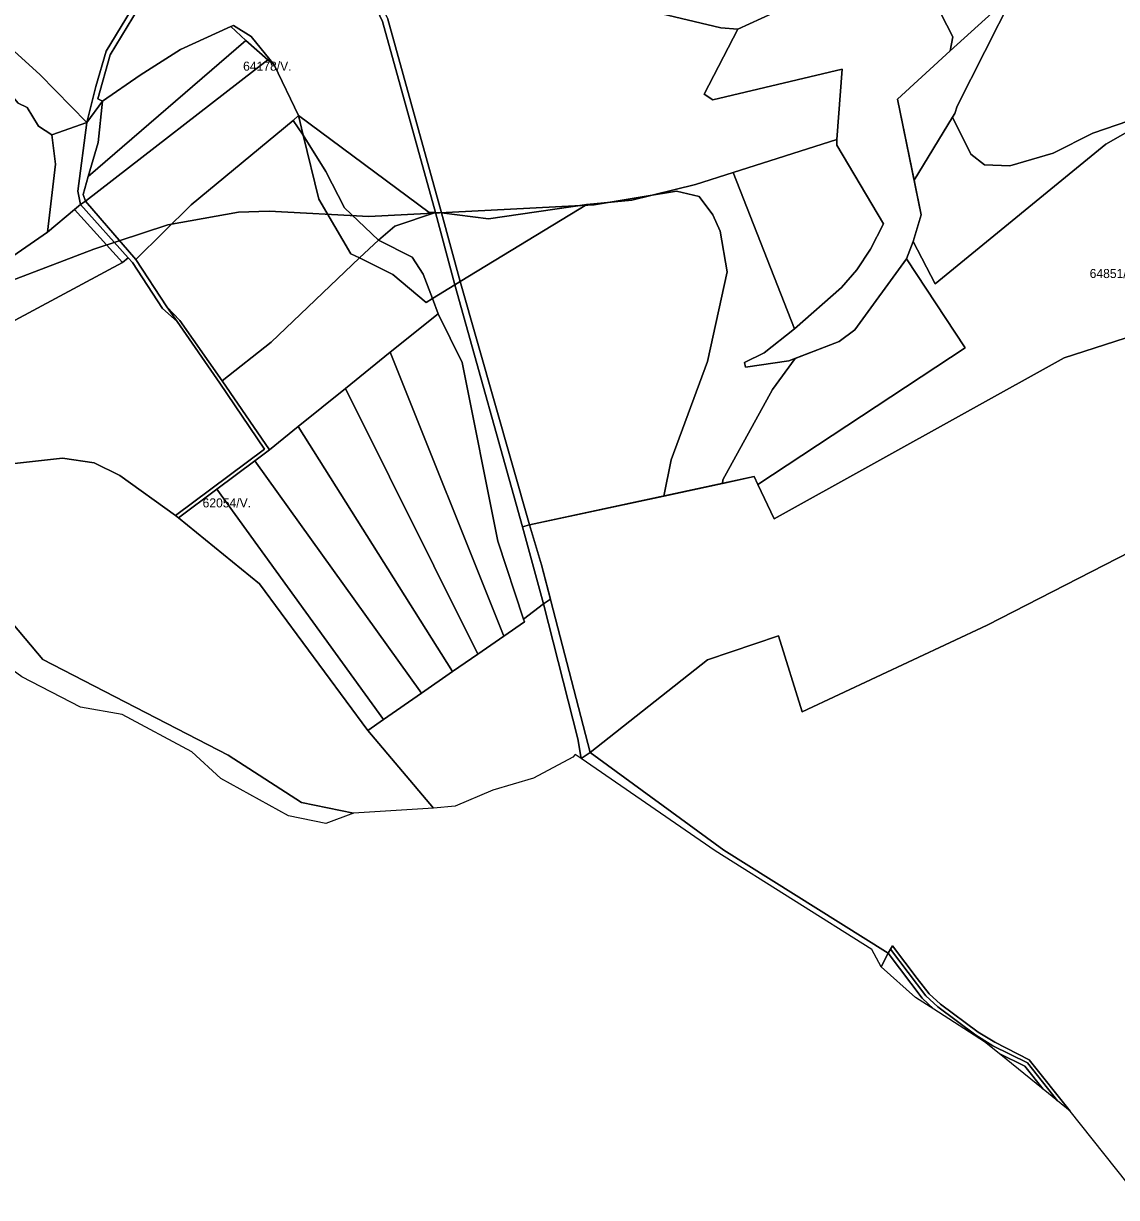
# Model space of a CAD drawing. Extents: x -521261 to -517465, y -1182764 to -1179456.
# Drawn here: x -518839 to -518235, y -1182709 to -1182060 of the extents above; entities that cross this region are included whole.
import ezdxf

# ---------------------------------------------------------------- set-up
doc = ezdxf.new("R2010")
doc.units = 0
for name, color, linetype in [('95560013', 7, 'Continuous'), ('95610013', 7, 'Continuous'), ('95620013', 7, 'Continuous'), ('95640013', 7, 'Continuous'), ('95660013', 7, 'Continuous')]:
    doc.layers.add(name, color=color, linetype=linetype)

msp = doc.modelspace()

# ---------------------------------------------------------------- linework, layer by layer
at = {"layer": '95560013'}
for points in [[(-517937.47, -1181926.51), (-517884.7, -1181968.01), (-518025.29, -1182113.9), (-518027.56, -1182111.28), (-518111.08, -1182158.35), (-518153.43, -1182170.1), (-518139.38, -1182204.87), (-518263.83, -1182245.02), (-518424.06, -1182333.99), (-518433.13, -1182315.06), (-518318.58, -1182239.54), (-518350.96, -1182190.35), (-518347.31, -1182180.7), (-518335.12, -1182204.11), (-518240.87, -1182127.03), (-518183.99, -1182094.63), (-518090.51, -1182068.93), (-518110.82, -1182018.11), (-518086.87, -1182044.67), (-518069.54, -1182031.68), (-518065.44, -1182028.22), (-518074.66, -1182003.92), (-518054.75, -1182013.18), (-518003.38, -1181979.84)], [(-518167.73, -1181955), (-518110.82, -1182018.11), (-518090.51, -1182068.93), (-518183.99, -1182094.63), (-518240.87, -1182127.03), (-518335.12, -1182204.11), (-518347.31, -1182180.7), (-518342.86, -1182166.04), (-518356.01, -1182102.22), (-518326.89, -1182075.42), (-518296.03, -1182047.39), (-518203.6, -1181987.3), (-518203.86, -1181976.19)], [(-518700.25, -1182083.11), (-518686.86, -1182111.13), (-518689.9, -1182113.86), (-518746.1, -1182160.51), (-518776.69, -1182190.71), (-518804.47, -1182158.53), (-518703.84, -1182080.32)], [(-518689.9, -1182113.86), (-518684.29, -1182121.97), (-518675.72, -1182157.46), (-518658.04, -1182187.51), (-518653.23, -1182189.87), (-518702, -1182236.38), (-518728.96, -1182257.76), (-518752.35, -1182224.39), (-518759.58, -1182216.94), (-518776.69, -1182190.71), (-518746.1, -1182160.51)], [(-518689.9, -1182113.86), (-518686.86, -1182111.13), (-518684.29, -1182121.97)], [(-518686.86, -1182111.13), (-518614.61, -1182164.68), (-518611.24, -1182164.8), (-518633.66, -1182172.36), (-518642.72, -1182180.05), (-518661.49, -1182162.15), (-518671.83, -1182142.12), (-518684.29, -1182121.97)], [(-518684.29, -1182121.97), (-518671.83, -1182142.12), (-518661.49, -1182162.15), (-518642.72, -1182180.05), (-518653.23, -1182189.87), (-518658.04, -1182187.51), (-518675.72, -1182157.46)], [(-518446.76, -1182142.75), (-518412.83, -1182229.01), (-518429.66, -1182242.3), (-518440.48, -1182247.57), (-518439.99, -1182250.28), (-518416.09, -1182246.77), (-518388.22, -1182235.99), (-518379.47, -1182229.52), (-518350.96, -1182190.35), (-518318.58, -1182239.54), (-518433.13, -1182315.06), (-518435.2, -1182310.64), (-518559.26, -1182337.41), (-518597.56, -1182202.93), (-518527.66, -1182160.32), (-518502.65, -1182158.02), (-518467.48, -1182149.36)], [(-518804.47, -1182158.53), (-518776.69, -1182190.71), (-518759.58, -1182216.94), (-518753.86, -1182224.98), (-518761.94, -1182217.74), (-518778.49, -1182192.42), (-518780.9, -1182189.83), (-518807.22, -1182160.43)], [(-518810.55, -1182163.14), (-518784.05, -1182192.34), (-518855.87, -1182230.85), (-518949.78, -1182265.77), (-518957.97, -1182261.15), (-518966.08, -1182237.71), (-518940.53, -1182228.04), (-518928.17, -1182223.92), (-518863.4, -1182201.85), (-518825.45, -1182175.55)], [(-518807.22, -1182160.43), (-518780.9, -1182189.83), (-518784.05, -1182192.34), (-518810.55, -1182163.14)], [(-518611.24, -1182164.8), (-518600.56, -1182204.73), (-518612.93, -1182212.35), (-518617.97, -1182198.92), (-518624.12, -1182189.53), (-518642.72, -1182180.05), (-518633.66, -1182172.36)], [(-518607.85, -1182165.03), (-518597.56, -1182202.93), (-518600.56, -1182204.73), (-518611.24, -1182164.8)], [(-518527.66, -1182160.32), (-518597.56, -1182202.93), (-518607.85, -1182165.03), (-518581.87, -1182168.26)], [(-518624.12, -1182189.53), (-518617.97, -1182198.92), (-518612.93, -1182212.35), (-518616.36, -1182214.44), (-518634.78, -1182198.94), (-518653.23, -1182189.87), (-518642.72, -1182180.05)], [(-518784.05, -1182192.34), (-518780.9, -1182189.83), (-518778.49, -1182192.42), (-518761.94, -1182217.74), (-518753.86, -1182224.98), (-518730.33, -1182259.05), (-518705.7, -1182295.48), (-518754.91, -1182332.21), (-518785.58, -1182309.98), (-518799.71, -1182303), (-518817.23, -1182300.45), (-518852.15, -1182304.44), (-518880.01, -1182306.19), (-518905.94, -1182299.56), (-518929.3, -1182288.2), (-518949.78, -1182265.77), (-518855.87, -1182230.85)], [(-518653.23, -1182189.87), (-518634.78, -1182198.94), (-518616.36, -1182214.44), (-518612.93, -1182212.35), (-518609.8, -1182220.66), (-518636.22, -1182242), (-518660.98, -1182261.99), (-518687.02, -1182283.01), (-518702.93, -1182295.87), (-518728.96, -1182257.76), (-518702, -1182236.38)], [(-518612.93, -1182212.35), (-518600.56, -1182204.73), (-518563.11, -1182338.38), (-518551.47, -1182380.97), (-518562.67, -1182389.49), (-518576.74, -1182346.42), (-518596.5, -1182247.68), (-518609.8, -1182220.66)], [(-518597.56, -1182202.93), (-518559.26, -1182337.41), (-518563.11, -1182338.38), (-518600.56, -1182204.73)], [(-518759.58, -1182216.94), (-518752.35, -1182224.39), (-518728.96, -1182257.76), (-518702.93, -1182295.87), (-518711.08, -1182301.98), (-518731.97, -1182317.68), (-518753.1, -1182333.54), (-518754.91, -1182332.21), (-518705.7, -1182295.48), (-518730.33, -1182259.05), (-518753.86, -1182224.98)], [(-518636.22, -1182242), (-518609.8, -1182220.66), (-518596.5, -1182247.68), (-518576.74, -1182346.42), (-518562.67, -1182389.49), (-518562.01, -1182390.85), (-518573.44, -1182398.77)], [(-518660.98, -1182261.99), (-518636.22, -1182242), (-518573.44, -1182398.77), (-518587.82, -1182408.73)], [(-518687.02, -1182283.01), (-518660.98, -1182261.99), (-518587.82, -1182408.73), (-518601.78, -1182418.4)], [(-518702.93, -1182295.87), (-518687.02, -1182283.01), (-518601.78, -1182418.4), (-518618.86, -1182430.24), (-518711.08, -1182301.98)], [(-518799.71, -1182303), (-518785.58, -1182309.98), (-518754.91, -1182332.21), (-518753.1, -1182333.54), (-518708.42, -1182369.96), (-518648.65, -1182450.88), (-518612.29, -1182493.83), (-518656.41, -1182496.56), (-518685.18, -1182490.81), (-518725.77, -1182464.65), (-518828.06, -1182411.68), (-518865.37, -1182367.72), (-518852.15, -1182304.44), (-518817.23, -1182300.45)], [(-518731.97, -1182317.68), (-518711.08, -1182301.98), (-518618.86, -1182430.24), (-518640.01, -1182444.89)], [(-518753.1, -1182333.54), (-518731.97, -1182317.68), (-518640.01, -1182444.89), (-518648.65, -1182450.88), (-518708.42, -1182369.96)]]:
    msp.add_lwpolyline(points, close=True, dxfattribs=at)
at = {"layer": '95610013'}
for points in [[(-518762.93, -1181945.84), (-518735.59, -1181944.64), (-518720.24, -1181948.49), (-518709.38, -1181958.17), (-518725.01, -1181970.47), (-518741.93, -1181991.3), (-518793.08, -1182075.55), (-518798.87, -1182095.21), (-518803.83, -1182115.05), (-518829.83, -1182088.59), (-518858.12, -1182062.9), (-518889.08, -1182041.43), (-518875.98, -1182033.84), (-518827.3, -1181989.81), (-518772.88, -1181947.46)], [(-518708.15, -1181959.43), (-518724.45, -1181974.21), (-518740.82, -1181994.92), (-518790.95, -1182077.71), (-518797.78, -1182101.99), (-518795.23, -1182103.31), (-518803.83, -1182115.05), (-518798.87, -1182095.21), (-518793.08, -1182075.55), (-518741.93, -1181991.3), (-518725.01, -1181970.47), (-518709.38, -1181958.17)], [(-518724.45, -1181974.21), (-518708.15, -1181959.43), (-518686.54, -1181980.93), (-518658.7, -1182020.15), (-518640.52, -1182059.28), (-518611.24, -1182164.8), (-518614.61, -1182164.68), (-518686.86, -1182111.13), (-518700.25, -1182083.11), (-518713.09, -1182067.46), (-518722.81, -1182061.39), (-518724.32, -1182062.07), (-518751.97, -1182074.61), (-518774.42, -1182088.9), (-518795.23, -1182103.31), (-518797.78, -1182101.99), (-518790.95, -1182077.71), (-518740.82, -1181994.92)], [(-518510.09, -1182043.38), (-518444.47, -1182035.28), (-518420.88, -1182053.43), (-518424.84, -1182054.69), (-518444.19, -1182063.4), (-518453.63, -1182062.64), (-518490.02, -1182054.06), (-518504.2, -1182054.05)], [(-518724.32, -1182062.07), (-518715.88, -1182069.82), (-518802.99, -1182144.82), (-518797.55, -1182126.13), (-518795.23, -1182103.31), (-518774.42, -1182088.9), (-518751.97, -1182074.61)], [(-518722.81, -1182061.39), (-518713.09, -1182067.46), (-518700.25, -1182083.11), (-518703.84, -1182080.32), (-518715.88, -1182069.82), (-518724.32, -1182062.07)], [(-518865.04, -1182069.45), (-518861.95, -1182080.69), (-518853.17, -1182091.09), (-518841.68, -1182104.3), (-518836.85, -1182106.7), (-518830.45, -1182117.06), (-518823.16, -1182121.89), (-518821.12, -1182138.11), (-518825.45, -1182175.55), (-518863.4, -1182201.85), (-518928.17, -1182223.92), (-518954.27, -1182165.24), (-518970.44, -1182168.59), (-518984.8, -1182153.5), (-519002.24, -1182131.47), (-518974.87, -1182115.84), (-518955.62, -1182102.6), (-518935.43, -1182082.05), (-518859.47, -1182146.72), (-518853.31, -1182128.3), (-518897.42, -1182099.88), (-518890.47, -1182081.22), (-518878.76, -1182064.07)], [(-518703.84, -1182080.32), (-518804.47, -1182158.53), (-518805.75, -1182154.86), (-518802.99, -1182144.82), (-518715.88, -1182069.82)], [(-518795.23, -1182103.31), (-518797.55, -1182126.13), (-518802.99, -1182144.82), (-518805.75, -1182154.86), (-518804.47, -1182158.53), (-518807.22, -1182160.43), (-518808.76, -1182153.03), (-518803.83, -1182115.05)], [(-518803.83, -1182115.05), (-518808.76, -1182153.03), (-518807.22, -1182160.43), (-518810.55, -1182163.14), (-518825.45, -1182175.55), (-518821.12, -1182138.11), (-518823.16, -1182121.89)], [(-518389.49, -1182127.53), (-518363.62, -1182170.97), (-518370.83, -1182185.07), (-518378.46, -1182196.42), (-518386.94, -1182206.15), (-518412.83, -1182229.01), (-518446.76, -1182142.75), (-518389.43, -1182124.42)]]:
    msp.add_lwpolyline(points, close=True, dxfattribs=at)
msp.add_lwpolyline([(-518490.02, -1182054.06), (-518453.63, -1182062.64), (-518444.19, -1182063.4), (-518462.82, -1182099.41), (-518458.01, -1182102.44), (-518386.6, -1182085.52), (-518389.43, -1182124.42), (-518446.76, -1182142.75), (-518467.48, -1182149.36), (-518502.65, -1182158.02), (-518527.66, -1182160.32), (-518581.87, -1182168.26), (-518607.85, -1182165.03), (-518637.52, -1182058.03)], dxfattribs=at)
at = {"layer": '95620013'}
for points in [[(-518332.06, -1182054.74), (-518325.37, -1182067.68), (-518326.89, -1182075.42), (-518356.01, -1182102.22), (-518342.86, -1182166.04), (-518347.31, -1182180.7), (-518350.96, -1182190.35), (-518379.47, -1182229.52), (-518388.22, -1182235.99), (-518416.09, -1182246.77), (-518439.99, -1182250.28), (-518440.48, -1182247.57), (-518429.66, -1182242.3), (-518412.83, -1182229.01), (-518386.94, -1182206.15), (-518378.46, -1182196.42), (-518370.83, -1182185.07), (-518363.62, -1182170.97), (-518389.49, -1182127.53), (-518389.43, -1182124.42), (-518386.6, -1182085.52), (-518458.01, -1182102.44), (-518462.82, -1182099.41), (-518444.19, -1182063.4), (-518424.84, -1182054.69)], [(-518222.72, -1182708.99), (-518260.64, -1182661.33), (-518283.21, -1182633), (-518302.23, -1182623.19), (-518311.5, -1182617.7), (-518332.22, -1182602.24), (-518338.45, -1182596.45), (-518345.09, -1182588.03), (-518358.72, -1182569.94), (-518359.91, -1182571.84), (-518361.09, -1182574.04), (-518451.99, -1182517.08), (-518525.73, -1182463.17), (-518461.02, -1182411.93), (-518421.69, -1182398.59), (-518408.71, -1182440.57), (-518306.45, -1182392.72), (-518147.76, -1182311.32)]]:
    msp.add_lwpolyline(points, dxfattribs=at)
for points in [[(-518025.29, -1182113.9), (-518132.88, -1182226.29), (-518107.95, -1182268.17), (-518147.76, -1182311.32), (-518306.45, -1182392.72), (-518408.71, -1182440.57), (-518421.69, -1182398.59), (-518461.02, -1182411.93), (-518525.73, -1182463.17), (-518552.56, -1182359.4), (-518559.26, -1182337.41), (-518435.2, -1182310.64), (-518433.13, -1182315.06), (-518424.06, -1182333.99), (-518263.83, -1182245.02), (-518139.38, -1182204.87), (-518153.43, -1182170.1), (-518111.08, -1182158.35), (-518027.56, -1182111.28)], [(-518562.67, -1182389.49), (-518551.47, -1182380.97), (-518532.52, -1182455.61), (-518530.75, -1182466.4), (-518534.03, -1182464.13), (-518535.31, -1182465.71), (-518557.06, -1182477.23), (-518579.44, -1182483.85), (-518600.27, -1182492.68), (-518612.29, -1182493.83), (-518648.65, -1182450.88), (-518640.01, -1182444.89), (-518618.86, -1182430.24), (-518601.78, -1182418.4), (-518587.82, -1182408.73), (-518573.44, -1182398.77), (-518562.01, -1182390.85)], [(-518361.09, -1182574.04), (-518342.38, -1182598.83), (-518335.95, -1182604.96), (-518346.01, -1182598.51), (-518365, -1182581.49)], [(-518359.91, -1182571.84), (-518340.25, -1182597.6), (-518333.74, -1182603.69), (-518312.76, -1182619.3), (-518303.39, -1182625.12), (-518284.15, -1182634.6), (-518267.61, -1182655.55), (-518275.54, -1182649.17), (-518285.56, -1182636.5), (-518299.9, -1182629.46), (-518307.86, -1182623), (-518335.95, -1182604.96), (-518342.38, -1182598.83), (-518361.09, -1182574.04)], [(-518358.72, -1182569.94), (-518345.09, -1182588.03), (-518338.45, -1182596.45), (-518332.22, -1182602.24), (-518311.5, -1182617.7), (-518302.23, -1182623.19), (-518283.21, -1182633), (-518260.64, -1182661.33), (-518267.61, -1182655.55), (-518284.15, -1182634.6), (-518303.39, -1182625.12), (-518312.76, -1182619.3), (-518333.74, -1182603.69), (-518340.25, -1182597.6), (-518359.91, -1182571.84)], [(-518299.9, -1182629.46), (-518285.56, -1182636.5), (-518275.54, -1182649.17)]]:
    msp.add_lwpolyline(points, close=True, dxfattribs=at)
at = {"layer": '95640013'}
for points in [[(-518167.73, -1181955), (-518203.86, -1181976.19), (-518203.6, -1181987.3), (-518296.03, -1182047.39), (-518326.89, -1182075.42), (-518325.37, -1182067.68), (-518332.06, -1182054.74), (-518189.71, -1181930.34)], [(-518735.03, -1181941.6), (-518718.84, -1181946.08), (-518684.26, -1181979.3), (-518656.15, -1182018.67), (-518637.52, -1182058.03), (-518607.85, -1182165.03), (-518611.24, -1182164.8), (-518640.52, -1182059.28), (-518658.7, -1182020.15), (-518686.54, -1181980.93), (-518708.15, -1181959.43), (-518709.38, -1181958.17), (-518720.24, -1181948.49), (-518735.59, -1181944.64), (-518762.93, -1181945.84), (-518772.88, -1181947.46), (-518768, -1181943.45), (-518760.29, -1181942.5)], [(-518880.73, -1182050.39), (-518889.08, -1182041.43), (-518858.12, -1182062.9), (-518829.83, -1182088.59), (-518803.83, -1182115.05), (-518823.16, -1182121.89), (-518830.45, -1182117.06), (-518836.85, -1182106.7), (-518841.68, -1182104.3), (-518853.17, -1182091.09), (-518861.95, -1182080.69), (-518865.04, -1182069.45), (-518878.76, -1182064.07), (-518876.94, -1182060.89)], [(-518563.11, -1182338.38), (-518559.26, -1182337.41), (-518552.56, -1182359.4), (-518525.73, -1182463.17), (-518530.75, -1182466.4), (-518532.52, -1182455.61), (-518551.47, -1182380.97)], [(-518865.37, -1182367.72), (-518828.06, -1182411.68), (-518725.77, -1182464.65), (-518685.18, -1182490.81), (-518656.41, -1182496.56), (-518671.74, -1182502.4), (-518692.39, -1182498.07), (-518729.72, -1182477.4), (-518745.79, -1182462.67), (-518784.2, -1182442.1), (-518807.32, -1182438.02), (-518839.75, -1182421.31), (-518846.6, -1182416.39), (-518872.51, -1182380.67)], [(-518525.73, -1182463.17), (-518451.99, -1182517.08), (-518361.09, -1182574.04), (-518365, -1182581.49), (-518370.23, -1182571.92), (-518456.78, -1182517.53), (-518530.75, -1182466.4)]]:
    msp.add_lwpolyline(points, close=True, dxfattribs=at)
at = {"layer": '95660013'}
for points in [[(-518228, -1182006), (-518239, -1182007), (-518260.5, -1182013.5), (-518271.5, -1182021), (-518292.5, -1182045.5), (-518323, -1182106), (-518324.24, -1182110.04), (-518325.55, -1182112.16), (-518346.82, -1182146.82), (-518356.01, -1182102.22), (-518326.89, -1182075.42), (-518325.37, -1182067.68), (-518332.06, -1182054.74), (-518189.71, -1181930.34)], [(-518196, -1182103), (-518248, -1182121), (-518270, -1182132), (-518294, -1182139), (-518308, -1182138.5), (-518315.5, -1182132.5), (-518325.55, -1182112.16), (-518324.24, -1182110.04), (-518323, -1182106), (-518292.5, -1182045.5), (-518271.5, -1182021), (-518260.5, -1182013.5), (-518239, -1182007), (-518228, -1182006)], [(-518424.84, -1182054.69), (-518444.19, -1182063.4), (-518462.82, -1182099.41), (-518458.01, -1182102.44), (-518386.6, -1182085.52), (-518389.43, -1182124.42), (-518389.49, -1182127.53), (-518363.62, -1182170.97), (-518370.83, -1182185.07), (-518378.46, -1182196.42), (-518386.94, -1182206.15), (-518412.83, -1182229.01), (-518429.66, -1182242.3), (-518440.48, -1182247.57), (-518439.99, -1182250.28), (-518416.09, -1182246.77), (-518412.43, -1182245.35), (-518425, -1182262.5), (-518452.5, -1182312.5), (-518452.7, -1182314.42), (-518485.13, -1182321.41), (-518481, -1182301.5), (-518461, -1182247), (-518450, -1182197.5), (-518454, -1182175), (-518458, -1182166), (-518465.5, -1182156), (-518478, -1182153), (-518496, -1182156), (-518523.5, -1182160.5), (-518648, -1182167), (-518703, -1182164), (-518720, -1182164.5), (-518759, -1182171.5), (-518800, -1182185), (-518869.5, -1182211.5)], [(-518332.06, -1182054.74), (-518325.37, -1182067.68), (-518326.89, -1182075.42), (-518356.01, -1182102.22), (-518346.82, -1182146.82), (-518342.86, -1182166.04), (-518347.31, -1182180.7), (-518350.96, -1182190.35), (-518379.47, -1182229.52), (-518388.22, -1182235.99), (-518412.43, -1182245.35), (-518416.09, -1182246.77), (-518439.99, -1182250.28), (-518440.48, -1182247.57), (-518429.66, -1182242.3), (-518412.83, -1182229.01), (-518386.94, -1182206.15), (-518378.46, -1182196.42), (-518370.83, -1182185.07), (-518363.62, -1182170.97), (-518389.49, -1182127.53), (-518389.43, -1182124.42), (-518386.6, -1182085.52), (-518458.01, -1182102.44), (-518462.82, -1182099.41), (-518444.19, -1182063.4), (-518424.84, -1182054.69)], [(-518139.38, -1182204.87), (-518263.83, -1182245.02), (-518424.06, -1182333.99), (-518433.13, -1182315.06), (-518435.2, -1182310.64), (-518452.7, -1182314.42), (-518452.5, -1182312.5), (-518425, -1182262.5), (-518412.43, -1182245.35), (-518388.22, -1182235.99), (-518379.47, -1182229.52), (-518350.96, -1182190.35), (-518347.31, -1182180.7), (-518342.86, -1182166.04), (-518346.82, -1182146.82), (-518325.55, -1182112.16), (-518315.5, -1182132.5), (-518308, -1182138.5), (-518294, -1182139), (-518270, -1182132), (-518248, -1182121), (-518196, -1182103)], [(-518869.5, -1182211.5), (-518800, -1182185), (-518759, -1182171.5), (-518720, -1182164.5), (-518703, -1182164), (-518648, -1182167), (-518523.5, -1182160.5), (-518496, -1182156), (-518478, -1182153), (-518465.5, -1182156), (-518458, -1182166), (-518454, -1182175), (-518450, -1182197.5), (-518461, -1182247), (-518481, -1182301.5), (-518485.13, -1182321.41), (-518559.26, -1182337.41), (-518552.56, -1182359.4), (-518547.65, -1182378.39), (-518551.47, -1182380.97), (-518562.67, -1182389.49), (-518562.01, -1182390.85), (-518573.44, -1182398.77), (-518587.82, -1182408.73), (-518601.78, -1182418.4), (-518618.86, -1182430.24), (-518640.01, -1182444.89), (-518648.65, -1182450.88), (-518612.29, -1182493.83), (-518656.41, -1182496.56), (-518671.74, -1182502.4), (-518692.39, -1182498.07), (-518729.72, -1182477.4), (-518745.79, -1182462.67), (-518784.2, -1182442.1), (-518807.32, -1182438.02), (-518839.75, -1182421.31)], [(-518222.72, -1182708.99), (-518260.64, -1182661.33), (-518267.61, -1182655.55), (-518275.54, -1182649.17), (-518299.9, -1182629.46), (-518307.86, -1182623), (-518335.95, -1182604.96), (-518346.01, -1182598.51), (-518365, -1182581.49), (-518370.23, -1182571.92), (-518456.78, -1182517.53), (-518530.75, -1182466.4), (-518534.03, -1182464.13), (-518535.31, -1182465.71), (-518557.06, -1182477.23), (-518579.44, -1182483.85), (-518600.27, -1182492.68), (-518612.29, -1182493.83), (-518648.65, -1182450.88), (-518640.01, -1182444.89), (-518618.86, -1182430.24), (-518601.78, -1182418.4), (-518587.82, -1182408.73), (-518573.44, -1182398.77), (-518562.01, -1182390.85), (-518562.67, -1182389.49), (-518551.47, -1182380.97), (-518547.65, -1182378.39), (-518552.56, -1182359.4), (-518559.26, -1182337.41), (-518485.13, -1182321.41), (-518452.7, -1182314.42), (-518435.2, -1182310.64), (-518433.13, -1182315.06), (-518424.06, -1182333.99), (-518263.83, -1182245.02), (-518139.38, -1182204.87)]]:
    msp.add_lwpolyline(points, dxfattribs=at)

# ---------------------------------------------------------------- texts
for s, rotation, p in [('64178/V.', 360, (-518717.48, -1182086.4)), ('64851/IV.', 0, (-518249.82, -1182200.97)), ('62054/V.', 360, (-518739.85, -1182327.7))]:
    msp.add_text(s, height=5, rotation=rotation, dxfattribs=at).set_placement(p)

doc.saveas('drawing.dxf')
